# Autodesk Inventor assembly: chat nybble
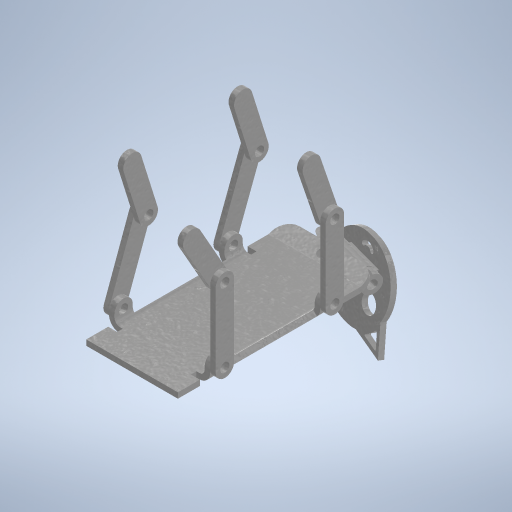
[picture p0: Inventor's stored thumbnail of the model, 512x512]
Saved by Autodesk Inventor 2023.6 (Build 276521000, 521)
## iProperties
Created: 2026-01
Part Number: chat nybble
Document SubType Name: Assembly
Designer: mel
Author: mel
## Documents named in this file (6)
- D:\travail\année 2025-2026\2CIT\chat nybble.iam
- D:\travail\année 2025-2026\2CIT\corps du chat.ipt
- D:\travail\année 2025-2026\2CIT\cuisse.ipt
- D:\travail\année 2025-2026\2CIT\mollet.ipt
- D:\travail\année 2025-2026\2CIT\machoire.ipt
- D:\travail\année 2025-2026\2CIT\tete.ipt
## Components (11 placed, 5 different names)
1. corps du chat:1 — Logement:1, Logement:3, Angle:1, Logement:4, Logement:5, Logement:6
2. cuisse:1 — Logement:1, Logement:2, Angle:2
3. mollet:1 — Logement:2
4. cuisse:2 — Logement:3, Angle:1, Angle:2, Logement:8
5. cuisse:3 — Logement:4, Logement:10
6. cuisse:4 — Logement:5, Logement:9
7. machoire:1 — Logement:6, Logement:7
8. tete:1 — Logement:7
9. mollet:2 — Logement:10
10. mollet:3 — Logement:9
11. mollet:4 — Logement:8
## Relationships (12: Insert 10, Angle 2)
- Logement:1 [Insert]: corps du chat:1 ↔ cuisse:1
- Logement:2 [Insert]: cuisse:1 ↔ mollet:1
- Logement:3 [Insert]: corps du chat:1 ↔ cuisse:2
- Angle:1: corps du chat:1 ↔ cuisse:2
- Angle:2: cuisse:1 ↔ cuisse:2
- Logement:4 [Insert]: corps du chat:1 ↔ cuisse:3
- Logement:5 [Insert]: corps du chat:1 ↔ cuisse:4
- Logement:6 [Insert]: corps du chat:1 ↔ machoire:1
- Logement:7 [Insert]: machoire:1 ↔ tete:1
- Logement:8 [Insert]: cuisse:2 ↔ mollet:4
- Logement:9 [Insert]: cuisse:4 ↔ mollet:3
- Logement:10 [Insert]: cuisse:3 ↔ mollet:2
